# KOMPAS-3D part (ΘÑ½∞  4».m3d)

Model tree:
1. Эскиз:1
2. Операция выдавливания:1
     Расстояние 1 = 2
3. Эскиз:2
4. Операция выдавливания:2
     Расстояние 1 = 5
5. Эскиз:3
6. Операция выдавливания:3
     Расстояние 1 = 2
7. Эскиз:4
8. Операция выдавливания:4
     Расстояние 1 = 78
9. Эскиз:5
10. Операция выдавливания:5
     Расстояние 1 = 2
11. Эскиз:6
12. Операция выдавливания:6
     Расстояние 1 = 4.5
13. Эскиз:7
14. Операция выдавливания:7
     Расстояние 1 = 2
15. Скругление:1
     Радиус = 1
16. Скругление:2
     Радиус = 1
17. Эскиз:8
18. Вырезать элемент выдавливания:1
     Расстояние 1 = 10; Угол 1 = 35
19. Эскиз:9
20. Вырезать элемент выдавливания:2
     Расстояние 1 = 10; Угол 1 = 35
21. Эскиз:10
22. Вырезать элемент выдавливания:3
     Расстояние 2 = 22; Расстояние 1 = 22; Угол 1 = 35
23. Эскиз:11
24. Вырезать элемент выдавливания:4
     Расстояние 2 = 2; Расстояние 1 = 2
25. Эскиз:12
26. Вырезать элемент выдавливания:5
     Расстояние 2 = 2; Расстояние 1 = 2; Угол 1 = 35
27. Эскиз:13
28. Вырезать элемент выдавливания:6
     Расстояние 2 = 2; Расстояние 1 = 122
29. Эскиз:14
30. Вырезать элемент выдавливания:7
     Расстояние 2 = 100; Расстояние 1 = 60
